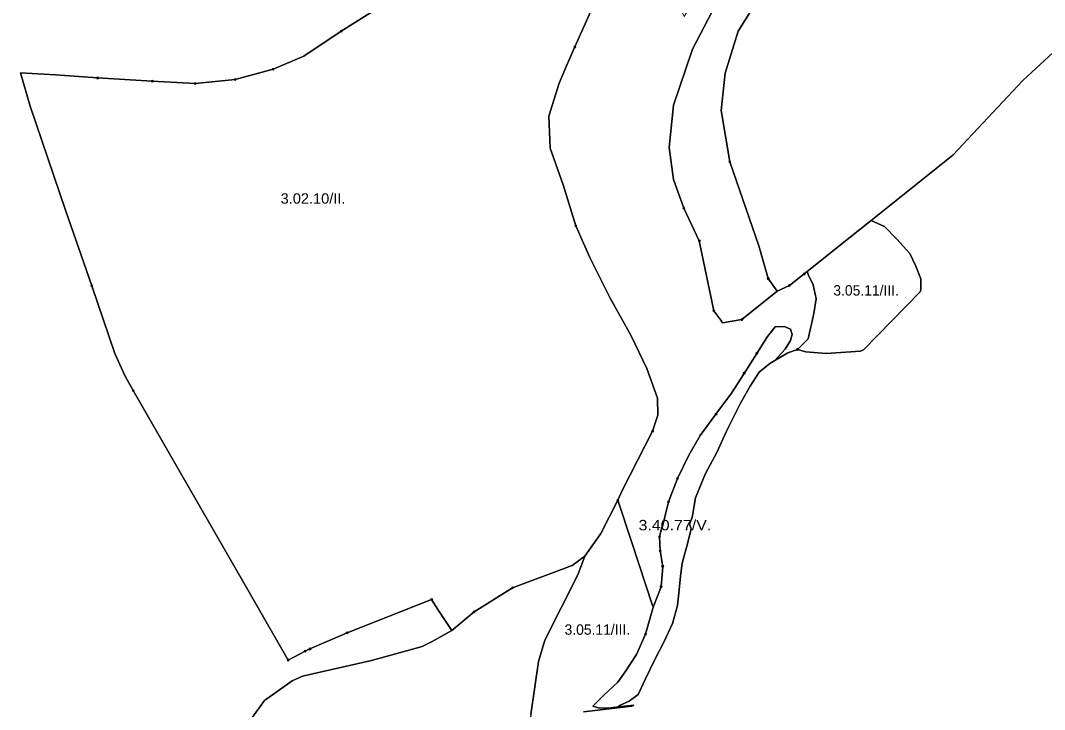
# Model space of a CAD drawing. Extents: x -650455 to -642254, y -1075222 to -1066610.
# Drawn here: x -646512 to -645525, y -1068906 to -1068242 of the extents above; entities that cross this region are included whole.
import ezdxf
from ezdxf.enums import TextEntityAlignment as Align

# ---------------------------------------------------------------- set-up
doc = ezdxf.new("R2010")
doc.units = 0
doc.header["$LTSCALE"] = 4
doc.header["$PDMODE"] = 32
doc.header["$PDSIZE"] = 2
for name, color, linetype, lineweight in [('1', 7, 'Continuous', 25), ('11', 7, 'Continuous', 13), ('12', 7, 'Continuous', 13), ('13', 7, 'Continuous', 13), ('14', 7, 'Continuous', 13), ('15', 7, 'Continuous', 13)]:
    doc.layers.add(name, color=color, linetype=linetype, lineweight=lineweight)
doc.layers.add('2', color=7, linetype='Continuous')

msp = doc.modelspace()

# ---------------------------------------------------------------- linework, layer by layer
at = {"layer": '1'}
for points in [[(-645508.5, -1067950.001), (-645526, -1067959.5), (-645546.5, -1067962.5), (-645595.5, -1067961.501), (-645607, -1067964), (-645620, -1067976.5), (-645623, -1068000), (-645622.5, -1068063.001), (-645628.5, -1068099.001), (-645636, -1068112.5), (-645652, -1068128.001), (-645711.5, -1068147.001), (-645729, -1068156.501), (-645769.5, -1068189.001), (-645806.5, -1068229.501), (-645820.5, -1068252.001), (-645833, -1068292.501), (-645837, -1068328.5), (-645828.5, -1068378.001), (-645800.5, -1068459.001), (-645791.5, -1068490.5), (-645783, -1068502.5), (-645817, -1068530), (-645835.5, -1068533.001)], [(-645835.5, -1068533.001), (-645837.25, -1068530.626), (-645844, -1068521.5), (-645858, -1068454), (-645873, -1068422.501), (-645883, -1068395.001), (-645887, -1068364), (-645883, -1068323.5), (-645864.5, -1068269.501), (-645830.5, -1068204.001)], [(-645830.5, -1068204.001), (-645864.5, -1068269.501), (-645883, -1068323.5), (-645887, -1068364), (-645883, -1068395.001), (-645873, -1068422.501), (-645858, -1068454), (-645844, -1068521.5), (-645837.25, -1068530.626), (-645835.5, -1068533.001), (-645817, -1068530), (-645783, -1068502.5), (-645771, -1068497), (-645757, -1068486), (-645754.063, -1068483.625), (-645754.054, -1068483.65), (-645753.062, -1068486.376), (-645748.375, -1068496.625), (-645745.188, -1068510), (-645747.562, -1068524.125), (-645753.062, -1068548.501), (-645763.25, -1068558.626)], [(-646167, -1068229.375), (-646203.125, -1068252.001), (-646239.25, -1068276.126), (-646268.75, -1068288.751), (-646305.5, -1068298.626), (-646344.062, -1068302.375), (-646385.313, -1068300.126), (-646438, -1068297.125), (-646478.625, -1068294.125), (-646512.375, -1068292.25), (-646503, -1068324.25), (-646468.875, -1068424.5), (-646443.563, -1068497.376), (-646421.312, -1068562.75), (-646413.5, -1068580.251), (-646411.5, -1068584.501), (-646403.688, -1068598.376), (-646362.938, -1068669.125), (-646292.063, -1068792.5), (-646254.375, -1068858), (-646237.938, -1068849.5), (-646233.312, -1068847.375), (-646197.562, -1068831.751), (-646116, -1068799.625), (-646109.312, -1068810.126), (-646096.5, -1068829.5), (-646115.5, -1068840.001), (-646125, -1068845), (-646174, -1068858.5), (-646240.5, -1068873.5), (-646250.5, -1068878), (-646277, -1068897.001), (-646294, -1068920.001)], [(-646411.5, -1068584.501), (-646413.5, -1068580.251), (-646421.312, -1068562.75), (-646443.563, -1068497.376), (-646468.875, -1068424.5), (-646503, -1068324.25), (-646512.375, -1068292.25), (-646478.625, -1068294.125), (-646438, -1068297.125), (-646385.313, -1068300.126), (-646344.062, -1068302.375), (-646305.5, -1068298.626), (-646268.75, -1068288.751), (-646239.25, -1068276.126), (-646203.125, -1068252.001), (-646167, -1068229.375)], [(-645962.438, -1068232.625), (-645977.937, -1068267.25), (-645985.875, -1068285.501), (-645985.9, -1068285.558), (-645993.125, -1068302.125), (-646002.938, -1068334.001), (-646001.687, -1068364.75), (-645989.375, -1068400.25), (-645977.063, -1068439.625), (-645963.688, -1068470.25), (-645944.375, -1068508.625), (-645923.687, -1068545.75), (-645908.5, -1068577.001), (-645898.188, -1068605.625), (-645897.875, -1068622.125), (-645903, -1068637.501), (-645932.5, -1068694.501), (-645936.5, -1068704), (-645953, -1068736), (-645968.5, -1068758.001), (-645980.5, -1068767.001), (-646038, -1068788.5), (-646075, -1068811.501), (-646096.5, -1068829.5), (-646109.312, -1068810.126), (-646116, -1068799.625), (-646197.562, -1068831.751), (-646233.312, -1068847.375), (-646237.938, -1068849.5), (-646254.375, -1068858), (-646292.063, -1068792.5), (-646362.938, -1068669.125), (-646403.688, -1068598.376), (-646411.5, -1068584.501)], [(-645989.375, -1068400.25), (-646001.687, -1068364.75), (-646002.938, -1068334.001), (-645993.125, -1068302.125), (-645985.9, -1068285.558), (-645985.875, -1068285.501), (-645977.937, -1068267.25), (-645962.438, -1068232.625)], [(-645487.5, -1068245.501), (-645546, -1068299.5), (-645613.5, -1068371.5), (-645692.438, -1068434.501), (-645712.513, -1068450.504), (-645712.527, -1068450.515), (-645754.063, -1068483.625), (-645757, -1068486), (-645771, -1068497), (-645783, -1068502.5), (-645791.5, -1068490.5), (-645800.5, -1068459.001), (-645828.5, -1068378.001), (-645837, -1068328.5), (-645833, -1068292.501), (-645820.5, -1068252.001), (-645806.5, -1068229.501)], [(-645841.188, -1068657.875), (-645831.75, -1068637.375), (-645818.375, -1068610.626), (-645808.938, -1068594.126), (-645800.25, -1068580.751), (-645790.063, -1068572.125), (-645785.188, -1068569.251), (-645772.75, -1068561.876), (-645763.25, -1068558.626), (-645755.437, -1068561.125), (-645735.75, -1068562.626), (-645702.75, -1068560.251), (-645699.65, -1068559.035), (-645699.562, -1068559), (-645645.187, -1068503.251), (-645645.161, -1068503.178), (-645644.5, -1068501.376), (-645644.5, -1068490.751), (-645649.125, -1068478.5), (-645655.188, -1068466.25), (-645667.438, -1068452.5), (-645679.625, -1068440.376), (-645692.438, -1068434.501), (-645613.5, -1068371.5), (-645546, -1068299.5), (-645487.5, -1068245.501)], [(-645763.25, -1068558.626), (-645772.75, -1068561.876), (-645785.188, -1068569.251), (-645775.313, -1068558.5), (-645770.25, -1068550.25), (-645768.438, -1068544.251), (-645770.25, -1068539.25), (-645774.534, -1068537.109), (-645775.75, -1068536.501), (-645784.938, -1068536.875), (-645792.312, -1068546.126), (-645802.5, -1068562.5), (-645814.875, -1068581.751), (-645826.813, -1068601.001), (-645841.938, -1068621.125), (-645857.062, -1068641.751), (-645868.063, -1068660.5), (-645879.063, -1068683), (-645887.75, -1068705.501), (-645893.562, -1068729.5), (-645894.062, -1068730.001), (-645896.437, -1068739.375), (-645895.687, -1068752.75), (-645893.312, -1068767.751), (-645894.875, -1068787.375), (-645901.938, -1068805.5), (-645902.188, -1068806.126), (-645903, -1068805.5), (-645923.062, -1068744.626), (-645936.5, -1068704), (-645932.5, -1068694.501), (-645903, -1068637.501), (-645897.875, -1068622.125), (-645898.188, -1068605.625), (-645908.5, -1068577.001), (-645923.687, -1068545.75), (-645944.375, -1068508.625), (-645963.688, -1068470.25), (-645977.063, -1068439.625), (-645989.375, -1068400.25)], [(-645896.437, -1068739.375), (-645894.062, -1068730.001), (-645893.562, -1068729.5), (-645887.75, -1068705.501), (-645879.063, -1068683), (-645868.063, -1068660.5), (-645857.062, -1068641.751), (-645841.938, -1068621.125), (-645826.813, -1068601.001), (-645814.875, -1068581.751), (-645802.5, -1068562.5), (-645792.312, -1068546.126), (-645784.938, -1068536.875), (-645775.75, -1068536.501), (-645774.534, -1068537.109), (-645770.25, -1068539.25), (-645768.438, -1068544.251), (-645770.25, -1068550.25), (-645775.313, -1068558.5), (-645785.188, -1068569.251)], [(-645785.188, -1068569.251), (-645790.063, -1068572.125), (-645800.25, -1068580.751), (-645808.938, -1068594.126), (-645818.375, -1068610.626), (-645831.75, -1068637.375), (-645841.188, -1068657.875), (-645852.187, -1068678.251), (-645861.625, -1068701.875), (-645864.75, -1068720.75), (-645867.563, -1068727.125), (-645865.75, -1068731.501), (-645868.938, -1068744.876), (-645874.438, -1068764.626), (-645876, -1068777.126), (-645877.562, -1068790.501), (-645879.125, -1068805.5), (-645883.875, -1068822.751), (-645891.75, -1068840.125), (-645901.187, -1068858.126), (-645909.812, -1068876.251), (-645916.875, -1068891.25), (-645925.563, -1068897.501), (-645934.188, -1068901.501), (-645936.187, -1068903.25), (-645943.25, -1068904.001), (-645954.125, -1068904.375), (-645960.5, -1068902.626), (-645949.938, -1068892.001), (-645936.563, -1068879.376), (-645929.5, -1068869.25), (-645918.5, -1068852.625), (-645909.812, -1068833), (-645902.196, -1068806.154), (-645902.188, -1068806.126), (-645901.938, -1068805.5), (-645894.875, -1068787.375), (-645893.312, -1068767.751), (-645895.687, -1068752.75), (-645896.437, -1068739.375)], [(-645969.5, -1068908.001), (-645923, -1068902.5), (-645921.073, -1068901.633), (-645936.187, -1068903.25), (-645934.188, -1068901.501), (-645925.563, -1068897.501), (-645916.875, -1068891.25), (-645909.812, -1068876.251), (-645901.187, -1068858.126), (-645891.75, -1068840.125), (-645883.875, -1068822.751), (-645879.125, -1068805.5), (-645877.562, -1068790.501), (-645876, -1068777.126), (-645874.438, -1068764.626), (-645868.938, -1068744.876), (-645865.75, -1068731.501), (-645867.563, -1068727.125), (-645864.75, -1068720.75), (-645861.625, -1068701.875), (-645852.187, -1068678.251), (-645841.188, -1068657.875)], [(-646020.25, -1068910.376), (-646013, -1068859.501), (-646007, -1068839.001), (-645975, -1068776.001), (-645968.5, -1068758.001), (-645953, -1068736), (-645936.5, -1068704), (-645923.062, -1068744.626), (-645903, -1068805.5), (-645902.188, -1068806.126), (-645902.196, -1068806.154), (-645909.812, -1068833), (-645918.5, -1068852.625), (-645929.5, -1068869.25), (-645936.563, -1068879.376), (-645949.938, -1068892.001), (-645960.5, -1068902.626), (-645954.125, -1068904.375), (-645943.25, -1068904.001), (-645936.187, -1068903.25), (-645921.073, -1068901.633), (-645923, -1068902.5), (-645969.5, -1068908.001)], [(-646377, -1069080), (-646359, -1069068.5), (-646343.5, -1069054.001), (-646324.5, -1069023.5), (-646306, -1068951.5), (-646294, -1068920.001), (-646277, -1068897.001), (-646250.5, -1068878), (-646240.5, -1068873.5), (-646174, -1068858.5), (-646125, -1068845), (-646115.5, -1068840.001), (-646096.5, -1068829.5), (-646075, -1068811.501), (-646038, -1068788.5), (-645980.5, -1068767.001), (-645968.5, -1068758.001), (-645975, -1068776.001), (-646007, -1068839.001), (-646013, -1068859.501), (-646020.25, -1068910.376), (-646020.269, -1068910.381), (-646020.5, -1068912.001), (-646026.5, -1068930.5)]]:
    msp.add_lwpolyline(points, dxfattribs=at)
msp.add_lwpolyline([(-645763.25, -1068558.626), (-645753.062, -1068548.501), (-645747.562, -1068524.125), (-645745.188, -1068510), (-645748.375, -1068496.625), (-645753.062, -1068486.376), (-645754.054, -1068483.65), (-645754.063, -1068483.625), (-645712.527, -1068450.515), (-645712.513, -1068450.504), (-645692.438, -1068434.501), (-645679.625, -1068440.376), (-645667.438, -1068452.5), (-645655.188, -1068466.25), (-645649.125, -1068478.5), (-645644.5, -1068490.751), (-645644.5, -1068501.376), (-645645.161, -1068503.178), (-645645.187, -1068503.251), (-645699.562, -1068559), (-645699.65, -1068559.035), (-645702.75, -1068560.251), (-645735.75, -1068562.626), (-645755.437, -1068561.125)], close=True, dxfattribs=at)
at = {"layer": '11'}
for p, q in [((-646305.5, -1068298.626), (-646268.75, -1068288.751)), ((-646344.062, -1068302.375), (-646305.5, -1068298.626))]:
    msp.add_line(p, q, dxfattribs=at)
for points in [[(-646268.75, -1068288.751), (-646239.25, -1068276.126), (-646203.125, -1068252.001), (-646167, -1068229.375), (-646136.312, -1068209.001), (-646105.312, -1068170.75), (-646076.688, -1068131.501), (-646052.625, -1068095.375)], [(-645791.5, -1068490.5), (-645783, -1068502.5), (-645771, -1068497), (-645757, -1068486), (-645754.063, -1068483.625), (-645712.527, -1068450.515), (-645712.513, -1068450.504), (-645692.438, -1068434.501), (-645613.5, -1068371.5), (-645546, -1068299.5), (-645487.5, -1068245.501), (-645456, -1068226.5), (-645434.909, -1068222.163), (-645420.75, -1068219.25), (-645398.687, -1068220.501), (-645421.625, -1068203.625)], [(-645806.5, -1068229.501), (-645820.5, -1068252.001), (-645833, -1068292.501), (-645837, -1068328.5), (-645828.5, -1068378.001)], [(-645487.5, -1068245.501), (-645546, -1068299.5), (-645613.5, -1068371.5), (-645692.438, -1068434.501), (-645679.625, -1068440.376), (-645667.438, -1068452.5), (-645655.188, -1068466.25), (-645649.125, -1068478.5), (-645644.5, -1068490.751), (-645644.5, -1068501.376), (-645645.161, -1068503.178), (-645645.187, -1068503.251), (-645699.562, -1068559), (-645699.65, -1068559.035), (-645702.75, -1068560.251), (-645735.75, -1068562.626), (-645755.437, -1068561.125), (-645763.25, -1068558.626)], [(-646443.563, -1068497.376), (-646468.875, -1068424.5), (-646503, -1068324.25), (-646512.375, -1068292.25), (-646478.625, -1068294.125), (-646438, -1068297.125)], [(-646438, -1068297.125), (-646385.313, -1068300.126), (-646344.062, -1068302.375)], [(-645828.5, -1068378.001), (-645800.5, -1068459.001), (-645791.5, -1068490.5)], [(-646403.688, -1068598.376), (-646411.5, -1068584.501), (-646413.5, -1068580.251), (-646421.312, -1068562.75), (-646443.563, -1068497.376)], [(-645763.25, -1068558.626), (-645772.75, -1068561.876), (-645785.188, -1068569.251), (-645790.063, -1068572.125), (-645800.25, -1068580.751), (-645808.938, -1068594.126), (-645818.375, -1068610.626), (-645831.75, -1068637.375), (-645841.188, -1068657.875), (-645852.187, -1068678.251), (-645861.625, -1068701.875), (-645864.75, -1068720.75), (-645867.563, -1068727.125), (-645865.75, -1068731.501), (-645868.938, -1068744.876), (-645874.438, -1068764.626), (-645876, -1068777.126), (-645877.562, -1068790.501), (-645879.125, -1068805.5), (-645883.875, -1068822.751), (-645891.75, -1068840.125), (-645901.187, -1068858.126), (-645909.812, -1068876.251), (-645916.875, -1068891.25), (-645925.563, -1068897.501), (-645934.188, -1068901.501), (-645936.187, -1068903.25), (-645921.073, -1068901.633), (-645923, -1068902.5), (-645969.5, -1068908.001)], [(-646233.312, -1068847.375), (-646237.938, -1068849.5), (-646254.375, -1068858), (-646292.063, -1068792.5), (-646362.938, -1068669.125), (-646403.688, -1068598.376)], [(-646377, -1069080), (-646359, -1069068.5), (-646343.5, -1069054.001), (-646324.5, -1069023.5), (-646306, -1068951.5), (-646294, -1068920.001), (-646277, -1068897.001), (-646250.5, -1068878), (-646240.5, -1068873.5), (-646174, -1068858.5), (-646125, -1068845), (-646115.5, -1068840.001), (-646096.5, -1068829.5), (-646109.312, -1068810.126), (-646116, -1068799.625)], [(-646116, -1068799.625), (-646197.562, -1068831.751), (-646233.312, -1068847.375)]]:
    msp.add_lwpolyline(points, dxfattribs=at)
for p in [(-646268.75, -1068288.751), (-646438, -1068297.125), (-646305.5, -1068298.626), (-646344.062, -1068302.375), (-645828.5, -1068378.001), (-646443.563, -1068497.376), (-645763.25, -1068558.626), (-646403.688, -1068598.376), (-646116, -1068799.625), (-646233.312, -1068847.375)]:
    msp.add_point(p, dxfattribs=at)
at = {"layer": '12'}
for p, q in [((-645977.937, -1068267.25), (-645962.438, -1068232.625)), ((-646344.062, -1068302.375), (-646385.313, -1068300.126)), ((-646305.5, -1068298.626), (-646344.062, -1068302.375)), ((-646254.375, -1068858), (-646237.938, -1068849.5))]:
    msp.add_line(p, q, dxfattribs=at)
for points in [[(-646076.688, -1068131.501), (-646105.312, -1068170.75), (-646136.312, -1068209.001), (-646167, -1068229.375), (-646203.125, -1068252.001)], [(-646203.125, -1068252.001), (-646239.25, -1068276.126), (-646268.75, -1068288.751), (-646305.5, -1068298.626)], [(-645903, -1068637.501), (-645897.875, -1068622.125), (-645898.188, -1068605.625), (-645908.5, -1068577.001), (-645923.687, -1068545.75), (-645944.375, -1068508.625), (-645963.688, -1068470.25), (-645977.063, -1068439.625), (-645989.375, -1068400.25), (-646001.687, -1068364.75), (-646002.938, -1068334.001), (-645993.125, -1068302.125), (-645985.9, -1068285.558), (-645985.875, -1068285.501), (-645977.937, -1068267.25)], [(-646385.313, -1068300.126), (-646438, -1068297.125), (-646478.625, -1068294.125), (-646512.375, -1068292.25), (-646503, -1068324.25), (-646468.875, -1068424.5), (-646443.563, -1068497.376), (-646421.312, -1068562.75), (-646413.5, -1068580.251), (-646411.5, -1068584.501), (-646403.688, -1068598.376), (-646362.938, -1068669.125), (-646292.063, -1068792.5), (-646254.375, -1068858)], [(-645936.5, -1068704), (-645932.5, -1068694.501), (-645903, -1068637.501)], [(-646075, -1068811.501), (-646038, -1068788.5), (-645980.5, -1068767.001), (-645968.5, -1068758.001), (-645953, -1068736), (-645936.5, -1068704)], [(-646197.562, -1068831.751), (-646116, -1068799.625), (-646109.312, -1068810.126), (-646096.5, -1068829.5), (-646075, -1068811.501)], [(-646237.938, -1068849.5), (-646233.312, -1068847.375), (-646197.562, -1068831.751)]]:
    msp.add_lwpolyline(points, dxfattribs=at)
for p in [(-646203.125, -1068252.001), (-645977.937, -1068267.25), (-646305.5, -1068298.626), (-646385.313, -1068300.126), (-646344.062, -1068302.375), (-645903, -1068637.501), (-645936.5, -1068704), (-646075, -1068811.501), (-646197.562, -1068831.751), (-646237.938, -1068849.5), (-646254.375, -1068858)]:
    msp.add_point(p, dxfattribs=at)
at = {"layer": '13'}
for points in [[(-645677, -1067974.001), (-645677, -1067999), (-645677.381, -1068000), (-645681, -1068009.501), (-645697.5, -1068040.5), (-645731.5, -1068085.5), (-645830.5, -1068204.001), (-645864.5, -1068269.501), (-645883, -1068323.5), (-645887, -1068364), (-645883, -1068395.001), (-645873, -1068422.501), (-645858, -1068454), (-645844, -1068521.5)], [(-645791.5, -1068490.5), (-645800.5, -1068459.001), (-645828.5, -1068378.001), (-645837, -1068328.5), (-645833, -1068292.501), (-645820.5, -1068252.001), (-645806.5, -1068229.501), (-645769.5, -1068189.001)], [(-645844, -1068521.5), (-645837.25, -1068530.626), (-645835.5, -1068533.001), (-645817, -1068530), (-645783, -1068502.5), (-645791.5, -1068490.5)], [(-645969.5, -1068908.001), (-645923, -1068902.5), (-645921.073, -1068901.633), (-645936.187, -1068903.25), (-645943.25, -1068904.001), (-645954.125, -1068904.375), (-645960.5, -1068902.626), (-645949.938, -1068892.001), (-645936.563, -1068879.376), (-645929.5, -1068869.25), (-645918.5, -1068852.625), (-645909.812, -1068833), (-645902.196, -1068806.154), (-645902.188, -1068806.126), (-645903, -1068805.5), (-645923.062, -1068744.626), (-645936.5, -1068704), (-645953, -1068736), (-645968.5, -1068758.001), (-645975, -1068776.001), (-646007, -1068839.001), (-646013, -1068859.501), (-646020.25, -1068910.376)], [(-646241.5, -1069496.001), (-646193.5, -1069374.501), (-646167.5, -1069296), (-646158, -1069244.001), (-646160.5, -1069203.501), (-646183.5, -1069131.501), (-646202, -1069077.5), (-646206, -1069050.501), (-646201.5, -1069028), (-646192, -1069010.001), (-646156, -1068987.5), (-646026.5, -1068930.5), (-646020.5, -1068912.001), (-646020.269, -1068910.381), (-646020.25, -1068910.376), (-646013, -1068859.501), (-646007, -1068839.001), (-645975, -1068776.001), (-645968.5, -1068758.001), (-645980.5, -1068767.001), (-646038, -1068788.5)], [(-646038, -1068788.5), (-646075, -1068811.501), (-646096.5, -1068829.5), (-646115.5, -1068840.001), (-646125, -1068845), (-646174, -1068858.5), (-646240.5, -1068873.5), (-646250.5, -1068878), (-646277, -1068897.001), (-646294, -1068920.001)]]:
    msp.add_lwpolyline(points, dxfattribs=at)
msp.add_lwpolyline([(-645755.437, -1068561.125), (-645735.75, -1068562.626), (-645702.75, -1068560.251), (-645699.65, -1068559.035), (-645699.562, -1068559), (-645645.187, -1068503.251), (-645645.161, -1068503.178), (-645644.5, -1068501.376), (-645644.5, -1068490.751), (-645649.125, -1068478.5), (-645655.188, -1068466.25), (-645667.438, -1068452.5), (-645679.625, -1068440.376), (-645692.438, -1068434.501), (-645712.513, -1068450.504), (-645712.527, -1068450.515), (-645754.063, -1068483.625), (-645754.054, -1068483.65), (-645753.062, -1068486.376), (-645748.375, -1068496.625), (-645745.188, -1068510), (-645747.562, -1068524.125), (-645753.062, -1068548.501), (-645763.25, -1068558.626)], close=True, dxfattribs=at)
for p in [(-645791.5, -1068490.5), (-645844, -1068521.5), (-646038, -1068788.5)]:
    msp.add_point(p, dxfattribs=at)
at = {"layer": '14'}
for p, q in [((-645858, -1068454), (-645873, -1068422.501)), ((-645757, -1068486), (-645771, -1068497)), ((-645814.875, -1068581.751), (-645802.5, -1068562.5)), ((-645893.312, -1068767.751), (-645895.687, -1068752.75))]:
    msp.add_line(p, q, dxfattribs=at)
for points in [[(-645873, -1068422.501), (-645883, -1068395.001), (-645887, -1068364), (-645883, -1068323.5), (-645864.5, -1068269.501), (-645830.5, -1068204.001), (-645731.5, -1068085.5), (-645697.5, -1068040.5), (-645681, -1068009.501), (-645677.381, -1068000), (-645677, -1067999), (-645677, -1067974.001), (-645668, -1067933.501), (-645656, -1067915.5), (-645608, -1067885.5), (-645593, -1067870.5), (-645588.5, -1067857.001), (-645590.5, -1067834.5), (-645603, -1067803.001), (-645609.5, -1067776.001), (-645608.5, -1067747.501)], [(-645735.605, -1068000), (-645729.568, -1068015.238), (-645729.57, -1068015.25), (-645798.69, -1068122.171), (-645829.66, -1068168.341), (-645867.779, -1068230.191), (-645872.671, -1068238), (-645874.15, -1068234.441), (-645882.74, -1068213.72), (-645888.25, -1068200.251), (-645917.313, -1068130.126), (-645918.062, -1068130.501), (-645936.625, -1068169.376), (-645947.25, -1068193.626), (-645962.438, -1068232.625), (-645977.937, -1068267.25), (-645985.875, -1068285.501), (-645985.9, -1068285.558), (-645993.125, -1068302.125), (-646002.938, -1068334.001), (-646001.687, -1068364.75), (-645989.375, -1068400.25), (-645977.063, -1068439.625)], [(-645977.063, -1068439.625), (-645963.688, -1068470.25), (-645944.375, -1068508.625), (-645923.687, -1068545.75), (-645908.5, -1068577.001), (-645898.188, -1068605.625), (-645897.875, -1068622.125), (-645903, -1068637.501), (-645932.5, -1068694.501), (-645936.5, -1068704), (-645923.062, -1068744.626), (-645903, -1068805.5), (-645902.188, -1068806.126), (-645901.938, -1068805.5), (-645894.875, -1068787.375), (-645893.312, -1068767.751)], [(-645817, -1068530), (-645835.5, -1068533.001), (-645837.25, -1068530.626), (-645844, -1068521.5), (-645858, -1068454)], [(-645763.25, -1068558.626), (-645753.062, -1068548.501), (-645747.562, -1068524.125), (-645745.188, -1068510), (-645748.375, -1068496.625), (-645753.062, -1068486.376), (-645754.054, -1068483.65), (-645754.063, -1068483.625), (-645757, -1068486)], [(-645771, -1068497), (-645783, -1068502.5), (-645817, -1068530)], [(-645802.5, -1068562.5), (-645792.312, -1068546.126), (-645784.938, -1068536.875), (-645775.75, -1068536.501), (-645774.534, -1068537.109), (-645770.25, -1068539.25), (-645768.438, -1068544.251), (-645770.25, -1068550.25), (-645775.313, -1068558.5), (-645785.188, -1068569.251), (-645772.75, -1068561.876), (-645763.25, -1068558.626)], [(-645841.938, -1068621.125), (-645826.813, -1068601.001), (-645814.875, -1068581.751)], [(-645887.75, -1068705.501), (-645879.063, -1068683), (-645868.063, -1068660.5), (-645857.062, -1068641.751), (-645841.938, -1068621.125)], [(-645895.687, -1068752.75), (-645896.437, -1068739.375), (-645894.062, -1068730.001), (-645893.562, -1068729.5), (-645887.75, -1068705.501)]]:
    msp.add_lwpolyline(points, dxfattribs=at)
for p in [(-645873, -1068422.501), (-645977.063, -1068439.625), (-645858, -1068454), (-645757, -1068486), (-645771, -1068497), (-645817, -1068530), (-645802.5, -1068562.5), (-645763.25, -1068558.626), (-645814.875, -1068581.751), (-645841.938, -1068621.125), (-645887.75, -1068705.501), (-645895.687, -1068752.75), (-645893.312, -1068767.751)]:
    msp.add_point(p, dxfattribs=at)
at = {"layer": '15'}
for points in [[(-645909.812, -1068833), (-645918.5, -1068852.625), (-645929.5, -1068869.25), (-645936.563, -1068879.376), (-645949.938, -1068892.001), (-645960.5, -1068902.626), (-645954.125, -1068904.375), (-645943.25, -1068904.001), (-645936.187, -1068903.25), (-645934.188, -1068901.501), (-645925.563, -1068897.501), (-645916.875, -1068891.25), (-645909.812, -1068876.251), (-645901.187, -1068858.126), (-645891.75, -1068840.125), (-645883.875, -1068822.751), (-645879.125, -1068805.5), (-645877.562, -1068790.501), (-645876, -1068777.126), (-645874.438, -1068764.626), (-645868.938, -1068744.876), (-645865.75, -1068731.501), (-645867.563, -1068727.125), (-645864.75, -1068720.75), (-645861.625, -1068701.875), (-645852.187, -1068678.251), (-645841.188, -1068657.875), (-645831.75, -1068637.375), (-645818.375, -1068610.626), (-645808.938, -1068594.126), (-645800.25, -1068580.751), (-645790.063, -1068572.125), (-645785.188, -1068569.251), (-645775.313, -1068558.5), (-645770.25, -1068550.25), (-645768.438, -1068544.251), (-645770.25, -1068539.25), (-645774.534, -1068537.109), (-645775.75, -1068536.501), (-645784.938, -1068536.875)], [(-645784.938, -1068536.875), (-645792.312, -1068546.126), (-645802.5, -1068562.5), (-645814.875, -1068581.751), (-645826.813, -1068601.001), (-645841.938, -1068621.125), (-645857.062, -1068641.751), (-645868.063, -1068660.5), (-645879.063, -1068683)], [(-645879.063, -1068683), (-645887.75, -1068705.501), (-645893.562, -1068729.5), (-645894.062, -1068730.001), (-645896.437, -1068739.375)], [(-645896.437, -1068739.375), (-645895.687, -1068752.75), (-645893.312, -1068767.751), (-645894.875, -1068787.375)], [(-645894.875, -1068787.375), (-645901.938, -1068805.5), (-645902.188, -1068806.126), (-645902.196, -1068806.154), (-645909.812, -1068833)]]:
    msp.add_lwpolyline(points, dxfattribs=at)
for p in [(-645879.063, -1068683), (-645896.437, -1068739.375), (-645894.875, -1068787.375), (-645909.812, -1068833)]:
    msp.add_point(p, dxfattribs=at)

# ---------------------------------------------------------------- texts
at = {"layer": '2'}
for s, width, p in [('3.02.10/II.', 1.05, (-646230.351, -1068418.276)), ('3.40.77/V.', 1.15, (-645881.532, -1068732.993))]:
    msp.add_text(s, height=10, dxfattribs=dict(at, width=width)).set_placement(p, align=Align.CENTER)
for p in [(-645697.182, -1068506.812), (-645956.284, -1068833.655)]:
    msp.add_text('3.05.11/III.', height=10, dxfattribs=at).set_placement(p, align=Align.CENTER)

doc.saveas('drawing.dxf')
